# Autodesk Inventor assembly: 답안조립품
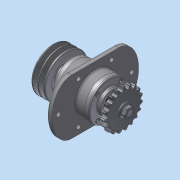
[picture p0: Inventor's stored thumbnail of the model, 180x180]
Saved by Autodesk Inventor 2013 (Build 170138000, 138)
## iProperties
Created: 2015-02
Part Number: 답안조립품
Document SubType Name: Assembly
Designer: Administrator
Author: Administrator
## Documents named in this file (12)
- C:\Users\Administrator\Desktop\450208V1008\답안조립품.iam
- C:\Users\Administrator\Desktop\450208V1008\본체.ipt
- C:\Users\Administrator\Desktop\450208V1008\2-커버.ipt
- C:\Users\Administrator\Desktop\450208V1008\3-축.ipt
- C:\Users\Administrator\Desktop\450208V1008\7-부시.ipt
- C:\Users\Administrator\Desktop\450208V1008\6-베어링 6206.ipt
- C:\Users\Administrator\Desktop\450208V1008\4-V벨트풀리.ipt
- C:\Users\Administrator\Desktop\450208V1008\5-체인 스프로킷.ipt
- C:\Users\Administrator\Desktop\450208V1008\8-오일실 30x42.ipt
- C:\Users\Administrator\Desktop\450208V1008\11-키 6x6.ipt
- C:\Users\Administrator\Desktop\450208V1008\9-M16-너트.ipt
- C:\Users\Administrator\Desktop\450208V1008\10-M6.ipt
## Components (22 placed, 10 different names)
1. 2-커버:1
2. 2-커버:2
3. 3-축:1
4. 7-부시:1
5. 6-베어링 6206:1
6. 6-베어링 6206:2
7. 4-V벨트풀리:1
8. 5-체인 스프로킷:1
9. 8-8-오일실 30x42:1
10. 11-키 6x6:1
11. 11-키 6x6:2
12. 8-8-오일실 30x42:2
13. 9-M16 너트:1 — 각도:3
14. 9-M16 너트:2 — 각도:4
15. 10-M6:1 — 각도:1
16. 10-M6:2
17. 10-M6:3
18. 10-M6:4
19. 10-M6:5 — 각도:2
20. 10-M6:6
21. 10-M6:7
22. 10-M6:8
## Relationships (4: Angle 4)
- 각도:1 [Angle]: 10-M6:1
- 각도:2 [Angle]: 10-M6:5
- 각도:3 [Angle]: 9-M16 너트:1
- 각도:4 [Angle]: 9-M16 너트:2
